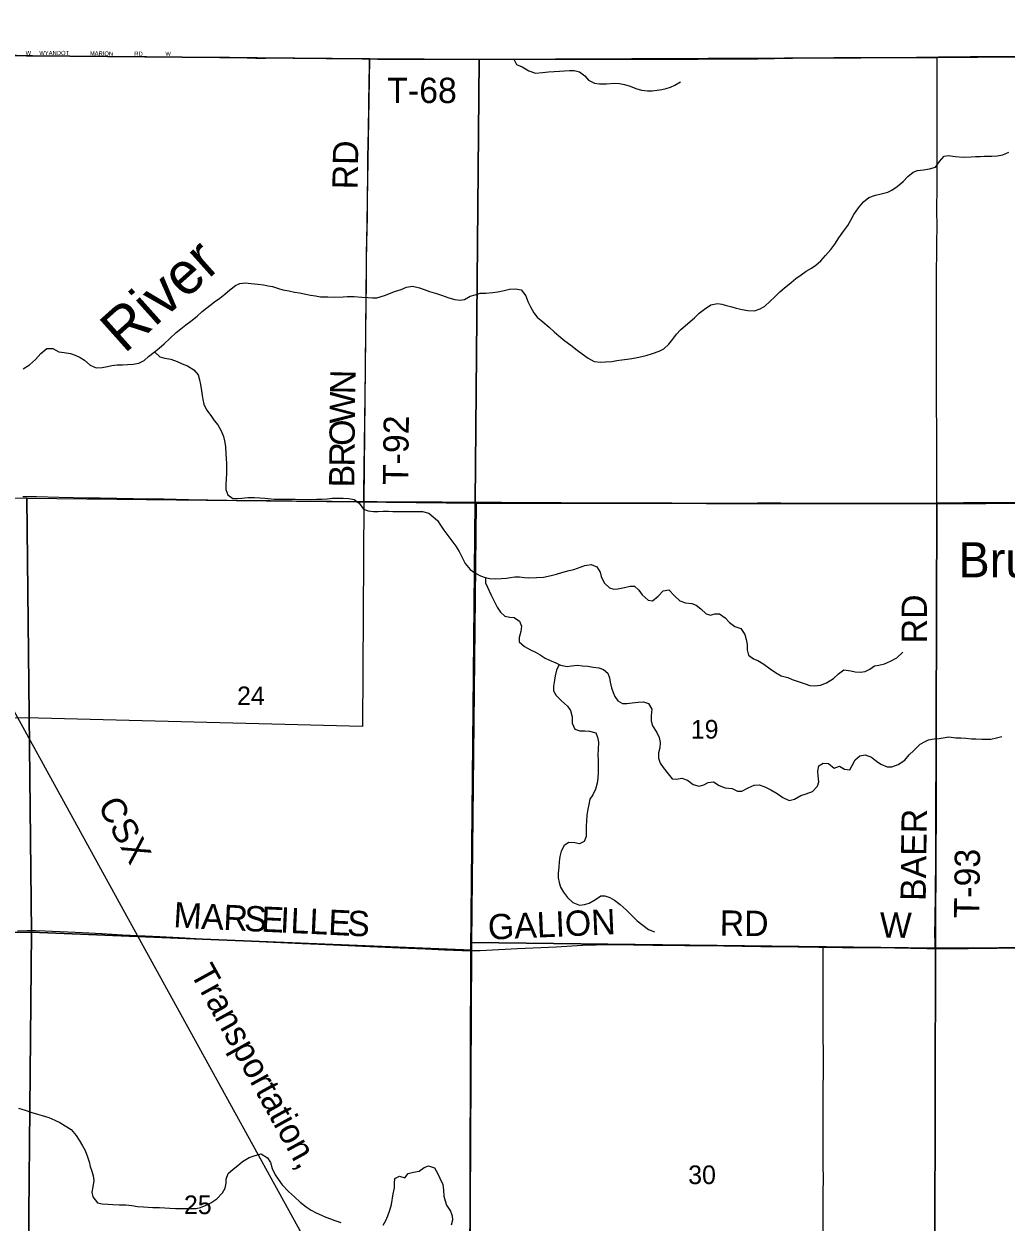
# Model space of a CAD drawing. Extents: x 1584893 to 1934202, y 663575 to 1091909.
# Drawn here: x 1772199 to 1783850, y 971203 to 985416 of the extents above; entities that cross this region are included whole.
import ezdxf

# ---------------------------------------------------------------- set-up
doc = ezdxf.new("R2010")
doc.units = 0
for name, color, linetype in [('GM_X_Adjacent_County', 7, 'Continuous'), ('GM_X_City_Street', 7, 'Continuous'), ('GM_X_City_Street_Text', 7, 'Continuous'), ('GM_X_Corporation', 7, 'Continuous'), ('GM_X_County', 7, 'Continuous'), ('GM_X_County_Road', 7, 'Continuous'), ('GM_X_County_Road_Text', 7, 'Continuous'), ('GM_X_Minor_River', 7, 'Continuous'), ('GM_X_Minor_River_Text', 7, 'Continuous'), ('GM_X_Rail_Line', 7, 'Continuous'), ('GM_X_Rail_Line_Text', 7, 'Continuous'), ('GM_X_Section', 7, 'Continuous'), ('GM_X_Section_Text', 7, 'Continuous'), ('GM_X_State_Route', 7, 'Continuous'), ('GM_X_Township', 7, 'Continuous'), ('GM_X_Township_Road', 7, 'Continuous'), ('GM_X_Township_Road_Text', 7, 'Continuous'), ('GM_X_Unincorporated_Text', 7, 'Continuous')]:
    doc.layers.add(name, color=color, linetype=linetype)

msp = doc.modelspace()

# ---------------------------------------------------------------- linework, layer by layer
at = {"layer": 'GM_X_Adjacent_County'}
msp.add_lwpolyline([(1798963, 1000818), (1798919, 995550), (1798958, 993982), (1798961, 990392), (1798944, 985119), (1793655, 985091), (1790446, 985072), (1788294, 985063), (1785879, 985049), (1785146, 985038), (1784945, 985035), (1783032, 985019), (1777600, 984996), (1776297, 985001), (1772302, 985037), (1771919, 985044), (1771012, 985062), (1767041, 985145), (1761103, 985171), (1756190, 985192)], dxfattribs=at)
at = {"layer": 'GM_X_City_Street'}
for points in [[(1771012, 985062), (1771168, 985059), (1771413, 985053), (1771919, 985044), (1772230, 985036), (1772273, 985036), (1772302, 985037)], [(1772302, 985037), (1772380, 985037), (1772948, 985033), (1773194, 985031), (1773651, 985029), (1773852, 985028), (1774030, 985027), (1774342, 985024), (1774473, 985023), (1774637, 985021), (1774949, 985012), (1775064, 985012), (1775277, 985014), (1775392, 985012), (1775556, 985009), (1775785, 985007), (1775900, 985006), (1776097, 985005), (1776212, 985002), (1776297, 985001)]]:
    msp.add_lwpolyline(points, dxfattribs=at)
at = {"layer": 'GM_X_Corporation'}
msp.add_lwpolyline([(1766961, 977231), (1766970, 979846), (1766980, 980279), (1766988, 980837), (1766989, 981036), (1767041, 985145), (1771012, 985062), (1771919, 985044), (1772302, 985037), (1776297, 985001), (1776257, 982591), (1776230, 979751), (1776216, 977083), (1772218, 977183), (1770900, 977182)], close=True, dxfattribs=at)
at = {"layer": 'GM_X_County'}
msp.add_lwpolyline([(1756190, 985192), (1761103, 985171), (1767041, 985145), (1771012, 985062), (1771919, 985044), (1772302, 985037), (1776297, 985001), (1777600, 984996), (1783032, 985019), (1784945, 985035), (1785146, 985038), (1785879, 985049), (1788294, 985063), (1790446, 985072), (1793655, 985091), (1798944, 985119), (1804246, 985060), (1804440, 985061), (1804717, 985058), (1805634, 985060), (1809554, 985051), (1810918, 985033)], dxfattribs=at)
at = {"layer": 'GM_X_County_Road'}
for points in [[(1772123, 974659), (1772237, 974662), (1772336, 974663), (1772451, 974658), (1772893, 974636), (1773123, 974624), (1773368, 974611), (1773549, 974602), (1773811, 974589), (1774040, 974577), (1774368, 974560), (1774908, 974533), (1775498, 974507), (1775695, 974498), (1775957, 974487), (1776301, 974471), (1776662, 974456), (1776957, 974444), (1777186, 974433), (1777399, 974424), (1777498, 974423), (1777508, 974423)], [(1777508, 974423), (1777612, 974426), (1778055, 974446), (1778513, 974469), (1778825, 974486), (1778989, 974493), (1779120, 974495), (1779432, 974492), (1779661, 974489), (1779858, 974487), (1780039, 974484), (1780285, 974482), (1780941, 974473), (1781384, 974468), (1781630, 974465), (1781679, 974464)], [(1781679, 974464), (1781909, 974461), (1782138, 974458), (1782532, 974454), (1782909, 974449), (1783007, 974449)], [(1781679, 971100), (1781679, 971255), (1781680, 971411), (1781682, 971534), (1781683, 971735), (1781682, 971856), (1781682, 971990), (1781680, 972188), (1781679, 972448), (1781680, 972559), (1781682, 972698), (1781682, 972829), (1781683, 972936), (1781683, 973084), (1781682, 973531), (1781682, 973707), (1781681, 973923), (1781681, 974183), (1781679, 974390), (1781679, 974445), (1781679, 974464)], [(1783007, 974449), (1783155, 974448), (1783401, 974449), (1783598, 974452), (1783746, 974453), (1783877, 974454), (1784123, 974456), (1784385, 974458), (1784763, 974460), (1785156, 974465), (1785632, 974469), (1786387, 974476), (1787043, 974483), (1787797, 974489), (1788240, 974493), (1788618, 974494), (1788733, 974494), (1788839, 974491)]]:
    msp.add_lwpolyline(points, dxfattribs=at)
at = {"layer": 'GM_X_Minor_River'}
for points in [[(1778009, 984997), (1778041, 984935), (1778111, 984908), (1778190, 984859), (1778268, 984832), (1778352, 984842), (1778422, 984849), (1778488, 984854), (1778552, 984856), (1778613, 984859), (1778669, 984862), (1778725, 984862), (1778789, 984849), (1778852, 984800), (1778896, 984750), (1778969, 984713), (1779025, 984704), (1779108, 984706), (1779200, 984713), (1779264, 984710), (1779322, 984699), (1779390, 984679), (1779459, 984650), (1779527, 984631), (1779595, 984622), (1779653, 984624), (1779711, 984629), (1779768, 984639), (1779818, 984650), (1779870, 984668), (1779920, 984689), (1779987, 984731)], [(1777010, 982243), (1777092, 982220), (1777153, 982198), (1777239, 982167), (1777311, 982146), (1777369, 982139), (1777425, 982147), (1777494, 982188), (1777550, 982204), (1777610, 982221), (1777680, 982224), (1777762, 982231), (1777819, 982239), (1777895, 982254), (1777961, 982269), (1778031, 982275), (1778099, 982260), (1778154, 982191), (1778178, 982123), (1778209, 982060), (1778248, 981990), (1778288, 981937), (1778353, 981881), (1778429, 981818), (1778488, 981765), (1778544, 981718), (1778617, 981657), (1778687, 981605), (1778760, 981548), (1778822, 981501), (1778892, 981450), (1778965, 981413), (1779037, 981405), (1779097, 981406), (1779174, 981413), (1779232, 981423), (1779292, 981432), (1779354, 981439), (1779412, 981449), (1779472, 981458), (1779529, 981470), (1779581, 981483), (1779657, 981506), (1779733, 981536), (1779790, 981563), (1779848, 981619), (1779897, 981678), (1779940, 981734), (1779988, 981786), (1780073, 981861), (1780154, 981930), (1780209, 981986), (1780273, 982033), (1780346, 982083), (1780426, 982100), (1780480, 982090), (1780532, 982077), (1780596, 982060), (1780648, 982046), (1780720, 982029), (1780788, 982018), (1780864, 982013), (1780934, 982035), (1780988, 982070), (1781047, 982124), (1781106, 982179), (1781166, 982237), (1781219, 982282), (1781302, 982348), (1781358, 982397), (1781419, 982439), (1781479, 982482), (1781542, 982518), (1781592, 982555), (1781651, 982605), (1781707, 982670), (1781770, 982742), (1781819, 982804), (1781868, 982879), (1781927, 982961), (1781973, 983027), (1782012, 983098), (1782043, 983156), (1782098, 983236), (1782160, 983307), (1782223, 983357), (1782301, 983384), (1782354, 983396), (1782446, 983419), (1782496, 983444), (1782557, 983488), (1782629, 983547), (1782684, 983607), (1782747, 983658), (1782801, 983676), (1782871, 983687), (1782941, 983696), (1783014, 983716), (1783062, 983783), (1783115, 983849), (1783167, 983856)], [(1783167, 983856), (1783245, 983842), (1783345, 983837), (1783437, 983840), (1783489, 983843), (1783542, 983845), (1783592, 983846), (1783680, 983849), (1783746, 983851), (1783810, 983864), (1783882, 983895)], [(1772191, 981326), (1772264, 981373), (1772334, 981435), (1772399, 981508), (1772470, 981564), (1772540, 981565), (1772614, 981528), (1772675, 981517), (1772751, 981507), (1772805, 981488), (1772865, 981459), (1772917, 981427), (1772984, 981368), (1773054, 981337), (1773126, 981340), (1773190, 981352), (1773241, 981363), (1773305, 981371), (1773369, 981374), (1773429, 981377), (1773495, 981381), (1773563, 981392), (1773626, 981424), (1773678, 981471), (1773743, 981523), (1773801, 981568), (1773862, 981620), (1773931, 981685), (1774005, 981754), (1774060, 981798), (1774118, 981846), (1774179, 981889), (1774252, 981948), (1774312, 982004), (1774458, 982119), (1774524, 982162), (1774581, 982212), (1774643, 982261), (1774710, 982315), (1774760, 982338), (1774822, 982346), (1774896, 982337), (1774972, 982328), (1775040, 982321), (1775096, 982309), (1775148, 982302), (1775218, 982277), (1775272, 982261), (1775342, 982250), (1775410, 982235), (1775466, 982225), (1775522, 982216), (1775598, 982197), (1775656, 982189), (1775718, 982180), (1775804, 982177), (1775884, 982174), (1775984, 982179), (1776034, 982183), (1776116, 982184), (1776206, 982175), (1776280, 982172), (1776332, 982168), (1776384, 982167), (1776477, 982196), (1776527, 982216), (1776595, 982241), (1776672, 982267), (1776738, 982294), (1776810, 982307), (1776890, 982286), (1776948, 982266), (1777010, 982243)], [(1773746, 981525), (1773810, 981468), (1773872, 981451), (1773942, 981438), (1774018, 981410), (1774074, 981385), (1774141, 981360), (1774215, 981313), (1774264, 981253), (1774280, 981194), (1774293, 981140), (1774307, 981064), (1774314, 981010), (1774322, 980959), (1774333, 980907), (1774364, 980837), (1774414, 980770), (1774457, 980713), (1774499, 980661), (1774540, 980590), (1774565, 980522), (1774579, 980470), (1774588, 980405), (1774593, 980313), (1774597, 980261), (1774600, 980197), (1774603, 980135), (1774603, 980076), (1774598, 980022), (1774595, 979948), (1774595, 979892), (1774616, 979828), (1774676, 979787), (1774732, 979788), (1774782, 979792), (1774856, 979799), (1774934, 979800), (1774996, 979796), (1775062, 979789), (1775166, 979780), (1775228, 979777), (1775290, 979779), (1775417, 979777), (1775599, 979776), (1775671, 979779), (1775733, 979780), (1775797, 979784), (1775857, 979789), (1775925, 979792), (1775987, 979790), (1776053, 979785), (1776117, 979776), (1776177, 979730), (1776228, 979661), (1776284, 979640), (1776346, 979634), (1776402, 979631), (1776460, 979635), (1776524, 979636), (1776574, 979633), (1776792, 979631), (1776857, 979633), (1776925, 979632), (1777001, 979613), (1777052, 979570), (1777106, 979526), (1777141, 979469), (1777179, 979411), (1777226, 979346), (1777275, 979285), (1777321, 979221), (1777360, 979156), (1777396, 979086), (1777433, 979017), (1777494, 978944), (1777546, 978906), (1777614, 978869), (1777669, 978850), (1777725, 978838), (1777795, 978835), (1777861, 978836), (1777922, 978842), (1777972, 978851), (1778022, 978857), (1778076, 978856), (1778136, 978850), (1778188, 978845), (1778280, 978848), (1778364, 978855), (1778452, 978871), (1778515, 978888), (1778581, 978907), (1778667, 978931), (1778723, 978944), (1778854, 978993), (1778926, 979002), (1778996, 978975), (1779033, 978911), (1779045, 978861), (1779082, 978786), (1779144, 978727)], [(1777673, 978850), (1777673, 978784), (1777743, 978639), (1777773, 978577), (1777812, 978498), (1777851, 978438), (1777905, 978389), (1777963, 978380), (1778015, 978376), (1778078, 978333), (1778102, 978271), (1778095, 978207), (1778072, 978137), (1778074, 978087), (1778139, 978032), (1778207, 977993), (1778267, 977962), (1778323, 977932), (1778382, 977893), (1778434, 977868), (1778508, 977836), (1778566, 977809), (1778643, 977794), (1778696, 977802), (1778764, 977809), (1778824, 977802), (1778888, 977798), (1778950, 977787), (1779020, 977778), (1779074, 977758), (1779127, 977713), (1779147, 977657), (1779154, 977606), (1779169, 977540), (1779189, 977486), (1779210, 977436), (1779244, 977385), (1779298, 977356), (1779352, 977354), (1779416, 977363), (1779486, 977371), (1779548, 977376), (1779610, 977353), (1779647, 977287), (1779638, 977207), (1779638, 977149), (1779655, 977088), (1779707, 977010), (1779736, 976953), (1779745, 976891), (1779741, 976829), (1779728, 976771), (1779725, 976705), (1779745, 976646), (1779784, 976596), (1779842, 976519), (1779887, 976462), (1779941, 976456), (1780003, 976467), (1780069, 976443), (1780137, 976392), (1780210, 976373), (1780265, 976388), (1780315, 976418), (1780379, 976425), (1780447, 976383), (1780519, 976352), (1780601, 976345), (1780664, 976316), (1780716, 976314), (1780791, 976355), (1780861, 976386), (1780921, 976388), (1780989, 976365), (1781061, 976332), (1781133, 976285), (1781200, 976239), (1781276, 976204), (1781342, 976219), (1781415, 976262), (1781479, 976284), (1781553, 976311), (1781612, 976375), (1781629, 976427), (1781621, 976497), (1781616, 976553), (1781628, 976613), (1781679, 976647), (1781745, 976642), (1781812, 976589), (1781873, 976609), (1781932, 976576), (1781996, 976567), (1782025, 976619), (1782058, 976685), (1782116, 976734), (1782178, 976746), (1782252, 976719), (1782314, 976670), (1782365, 976634), (1782441, 976605)], [(1779144, 978727), (1779196, 978711), (1779246, 978714), (1779324, 978729), (1779392, 978747), (1779442, 978748), (1779494, 978700), (1779533, 978643), (1779603, 978582), (1779655, 978572), (1779721, 978629), (1779784, 978691), (1779848, 978704), (1779918, 978631), (1779981, 978574), (1780049, 978550), (1780121, 978541), (1780173, 978520), (1780228, 978478), (1780292, 978419), (1780344, 978404), (1780394, 978418), (1780450, 978417), (1780517, 978372), (1780571, 978314), (1780633, 978267), (1780702, 978244), (1780752, 978174), (1780767, 978113), (1780778, 978053), (1780780, 977993), (1780793, 977927), (1780855, 977884), (1780907, 977865), (1780976, 977823), (1781050, 977766), (1781115, 977723), (1781183, 977684), (1781261, 977663), (1781313, 977641), (1781383, 977616), (1781468, 977587), (1781524, 977568), (1781578, 977564), (1781648, 977573), (1781721, 977598), (1781801, 977652), (1781864, 977707), (1781927, 977753), (1782007, 977740), (1782061, 977731), (1782123, 977725), (1782179, 977734), (1782233, 977760), (1782289, 977801), (1782340, 977811), (1782406, 977826), (1782478, 977855), (1782553, 977897), (1782624, 977964)], [(1778547, 977818), (1778517, 977751), (1778502, 977683), (1778492, 977631), (1778483, 977559), (1778482, 977503), (1778514, 977451), (1778575, 977388), (1778647, 977323), (1778682, 977271), (1778701, 977198), (1778703, 977122), (1778734, 977051), (1778794, 977031), (1778854, 977030), (1778908, 977026), (1778982, 977007), (1779005, 976954), (1779015, 976894), (1779012, 976808), (1779009, 976746), (1779012, 976680), (1779011, 976535), (1779008, 976469), (1779000, 976411), (1778981, 976339), (1778946, 976272), (1778911, 976220), (1778901, 976158), (1778888, 976102), (1778875, 976030), (1778871, 975960), (1778868, 975905), (1778867, 975775), (1778846, 975717), (1778790, 975688), (1778736, 975700), (1778662, 975705), (1778609, 975670), (1778571, 975604), (1778558, 975538), (1778549, 975478), (1778543, 975414), (1778538, 975342), (1778537, 975287), (1778547, 975229), (1778564, 975177), (1778598, 975118), (1778649, 975052), (1778709, 974993), (1778788, 974962), (1778848, 974970), (1778903, 974985), (1778979, 975030), (1779042, 975074), (1779092, 975071), (1779150, 975053), (1779203, 975022), (1779271, 974969), (1779342, 974908), (1779412, 974840), (1779473, 974775), (1779539, 974724), (1779608, 974675), (1779678, 974644)], [(1782441, 976605), (1782493, 976602), (1782572, 976632), (1782648, 976683), (1782701, 976744), (1782756, 976796), (1782830, 976871), (1782881, 976901), (1782931, 976923), (1782997, 976936), (1783055, 976939), (1783105, 976947), (1783170, 976958), (1783254, 976949), (1783314, 976947), (1783372, 976942), (1783440, 976937), (1783490, 976935), (1783562, 976930), (1783618, 976930), (1783668, 976933), (1783738, 976948), (1783800, 976964)], [(1772136, 972552), (1772212, 972529), (1772292, 972502), (1772358, 972484), (1772416, 972465), (1772492, 972442), (1772565, 972413), (1772623, 972383), (1772689, 972346), (1772760, 972299), (1772818, 972230), (1772853, 972176), (1772894, 972105), (1772926, 972051), (1772951, 971978), (1772971, 971916), (1772986, 971862), (1773003, 971806), (1773019, 971749), (1773026, 971697), (1773016, 971621), (1773005, 971557), (1773016, 971501), (1773072, 971432), (1773128, 971417), (1773194, 971415), (1773254, 971410), (1773334, 971405), (1773408, 971407), (1773480, 971398)], [(1773480, 971398), (1773546, 971387), (1773618, 971382), (1773672, 971380), (1773728, 971377), (1773808, 971376), (1773872, 971372), (1773930, 971369), (1773998, 971364), (1774070, 971364), (1774130, 971365), (1774240, 971364), (1774294, 971376), (1774361, 971403), (1774415, 971430), (1774488, 971478), (1774556, 971549), (1774585, 971605), (1774598, 971663), (1774598, 971713), (1774621, 971779), (1774681, 971829), (1774738, 971874), (1774793, 971920), (1774871, 971969), (1774941, 971992), (1775012, 972010), (1775087, 971965), (1775123, 971910), (1775142, 971836), (1775181, 971761), (1775213, 971711), (1775264, 971644), (1775339, 971565), (1775409, 971500), (1775476, 971438), (1775546, 971383), (1775605, 971344), (1775665, 971313), (1775727, 971285), (1775781, 971260), (1775837, 971240), (1775888, 971223), (1775960, 971196)], [(1776462, 971167), (1776491, 971223), (1776516, 971275), (1776540, 971343), (1776559, 971409), (1776580, 971539), (1776595, 971609), (1776596, 971659), (1776598, 971721), (1776653, 971746), (1776719, 971728), (1776757, 971779), (1776819, 971795), (1776886, 971806), (1776948, 971848), (1777000, 971869), (1777070, 971846), (1777109, 971776), (1777131, 971722), (1777168, 971649), (1777178, 971581), (1777181, 971511), (1777194, 971456), (1777212, 971402), (1777259, 971333), (1777278, 971275), (1777284, 971225), (1777267, 971165)]]:
    msp.add_lwpolyline(points, dxfattribs=at)
at = {"layer": 'GM_X_Rail_Line'}
msp.add_lwpolyline([(1783640, 956258), (1783519, 956485), (1783352, 956796), (1782890, 957631), (1782729, 957923), (1782630, 958110), (1782495, 958363), (1782431, 958480), (1782385, 958557), (1780582, 961821), (1780198, 962518), (1779487, 963811), (1778628, 965371), (1777525, 967376), (1776542, 969162), (1773550, 974593), (1770672, 979824), (1769928, 981176), (1769339, 982253), (1768902, 983060), (1768396, 983986), (1767773, 985118)], dxfattribs=at)
at = {"layer": 'GM_X_Section'}
for points in [[(1772232, 979790), (1772288, 974643), (1766937, 974569), (1766983, 979866)], [(1777563, 979732), (1777507, 974521), (1777507, 974427), (1772288, 974643), (1772232, 979790)], [(1783030, 979724), (1783012, 974453), (1777507, 974521), (1777563, 979732)], [(1788265, 979759), (1788243, 974478), (1783012, 974453), (1783030, 979724)], [(1766937, 974569), (1772288, 974643), (1772236, 969202), (1766881, 969263)], [(1772288, 974643), (1777507, 974427), (1777480, 969162), (1772236, 969202)], [(1777507, 974521), (1783012, 974453), (1783001, 969162), (1777480, 969162), (1777507, 974427)], [(1783012, 974453), (1788243, 974478), (1788271, 969190), (1783001, 969162)]]:
    msp.add_lwpolyline(points, close=True, dxfattribs=at)
at = {"layer": 'GM_X_State_Route'}
for points in [[(1772185, 979811), (1772349, 979809), (1772611, 979804), (1772955, 979796), (1773103, 979794), (1773300, 979791), (1773496, 979788), (1773857, 979782), (1774152, 979776), (1774611, 979768), (1775119, 979761), (1775643, 979755), (1775856, 979753), (1776053, 979752), (1776184, 979751), (1776230, 979751)], [(1776230, 979751), (1776391, 979749), (1776850, 979748), (1777161, 979745), (1777440, 979743), (1777570, 979744), (1777653, 979744), (1777866, 979743), (1778276, 979740), (1778572, 979739), (1778883, 979736), (1779260, 979736), (1779884, 979735), (1780408, 979733), (1780900, 979734), (1781179, 979735), (1781474, 979732), (1781851, 979731), (1782393, 979731), (1782704, 979733), (1783030, 979736), (1783032, 979736), (1783344, 979737), (1783721, 979738), (1783992, 979740)]]:
    msp.add_lwpolyline(points, dxfattribs=at)
at = {"layer": 'GM_X_Township'}
for points in [[(1756190, 985192), (1761103, 985171), (1767041, 985145), (1771012, 985062), (1771919, 985044), (1772302, 985037), (1776297, 985001), (1777600, 984996), (1777553, 979747), (1777500, 974427), (1777484, 969144), (1777421, 963835), (1774761, 963889), (1772077, 963906), (1768920, 963948), (1764172, 963989), (1755145, 964022)], [(1789219, 963906), (1781614, 963853), (1780304, 963849), (1779496, 963806), (1777421, 963835), (1777484, 969144), (1777500, 974427), (1777553, 979747), (1777600, 984996), (1783032, 985019), (1784945, 985035)]]:
    msp.add_lwpolyline(points, dxfattribs=at)
at = {"layer": 'GM_X_Township_Road'}
for points in [[(1776230, 979751), (1776230, 979802), (1776231, 979873), (1776235, 980152), (1776239, 980431), (1776244, 980710), (1776247, 981022), (1776251, 981268), (1776252, 981449), (1776253, 981580), (1776255, 981761), (1776258, 982057), (1776261, 982369), (1776262, 982500), (1776263, 982631), (1776264, 982713), (1776270, 982960), (1776273, 983140), (1776274, 983337), (1776277, 983649), (1776280, 983830), (1776286, 984158), (1776291, 984454), (1776295, 984750), (1776297, 984897), (1776297, 985001)], [(1776297, 985001), (1776392, 985000), (1776507, 984999), (1776769, 984999), (1776933, 984999), (1777081, 984999), (1777360, 984998), (1777623, 984998), (1777627, 984998)], [(1777627, 984998), (1778029, 984998), (1778328, 984998), (1778487, 984998), (1778739, 984999), (1778985, 984999), (1779165, 984999), (1779282, 985000), (1779494, 985000), (1779937, 984999), (1780199, 985000), (1780413, 985001), (1780905, 985003), (1781102, 985006), (1781315, 985012), (1781552, 985016), (1781808, 985019), (1781988, 985020), (1782198, 985019), (1782546, 985020), (1782789, 985021), (1782973, 985022), (1783004, 985022), (1783019, 985023), (1783034, 985024)], [(1783030, 979736), (1783029, 979884), (1783027, 980162), (1783028, 980359), (1783027, 980507), (1783025, 980983), (1783026, 981179), (1783026, 981343), (1783025, 981475), (1783024, 981606), (1783023, 981737), (1783024, 981999), (1783025, 982180), (1783026, 982311), (1783026, 982491), (1783027, 982688), (1783028, 982836), (1783031, 983000), (1783030, 983213), (1783032, 983475), (1783032, 983646), (1783033, 983756), (1783033, 983853), (1783033, 983967), (1783033, 984082), (1783033, 984197), (1783032, 984443), (1783033, 984640), (1783033, 984837), (1783034, 985024)], [(1783034, 985024), (1783049, 985025), (1783066, 985026), (1783181, 985026), (1783427, 985029), (1783723, 985030), (1783904, 985031), (1784129, 985036), (1784289, 985039), (1784393, 985039), (1784571, 985041), (1784766, 985044), (1784848, 985041), (1784866, 985042), (1784882, 985044), (1784892, 985046), (1784899, 985049), (1784914, 985057), (1784930, 985067)], [(1783007, 974449), (1783008, 974472), (1783008, 974539), (1783007, 974604), (1783010, 974817), (1783011, 974932), (1783012, 974949), (1783013, 975080), (1783014, 975178), (1783014, 975227), (1783017, 975407), (1783019, 975587), (1783021, 975718), (1783021, 975767), (1783023, 975832), (1783024, 975914), (1783024, 976061), (1783023, 976422), (1783025, 976832), (1783025, 977046), (1783026, 977374), (1783025, 977538), (1783024, 977751), (1783024, 977997), (1783026, 978571), (1783028, 978932), (1783029, 979277), (1783029, 979424), (1783030, 979572), (1783030, 979736)]]:
    msp.add_lwpolyline(points, dxfattribs=at)

# ---------------------------------------------------------------- texts
at = {"layer": 'GM_X_City_Street_Text'}
for s, rotation, p in [('W', 0, (1772219, 985047)), ('WYANDOT', 0, (1772381, 985047)), ('MARION', 358.9717, (1772980, 985043)), ('RD', 0, (1773508, 985038)), ('W', 0, (1773877, 985038))]:
    msp.add_text(s, height=50, rotation=rotation, dxfattribs=at).set_placement(p)
at = {"layer": 'GM_X_County_Road_Text'}
for s, rotation, p in [('M', 356.5659, (1773967, 974701)), ('A', 357.3504, (1774297, 974681)), ('R', 357.3523, (1774560, 974669)), ('S', 357.3526, (1774806, 974657)), ('E', 357.3505, (1775009, 974648)), ('I', 357.345, (1775233, 974638)), ('L', 357.3538, (1775356, 974632)), ('L', 357.3505, (1775580, 974622)), ('E', 357.3505, (1775804, 974611)), ('S', 357.3489, (1776028, 974601)), ('GALION', 2.5127, (1777709, 974552)), ('RD', 359.5064, (1780452, 974600)), ('W', 359.2708, (1782351, 974578))]:
    msp.add_text(s, height=300, rotation=rotation, dxfattribs=at).set_placement(p)
at = {"layer": 'GM_X_Minor_River_Text'}
msp.add_text('River', height=500.1, rotation=41.7941, dxfattribs=at).set_placement((1773391, 981497))
at = {"layer": 'GM_X_Rail_Line_Text'}
for s, rotation, p in [('CSX', 298.6946, (1773068, 976146)), ('Transportation,', 298.8586, (1774165, 974159))]:
    msp.add_text(s, height=299, rotation=rotation, dxfattribs=at).set_placement(p)
at = {"layer": 'GM_X_Section_Text'}
for s, p in [('24', (1774727, 977335)), ('19', (1780110, 976938)), ('30', (1780079, 971653)), ('25', (1774097, 971297))]:
    msp.add_text(s, height=221, rotation=0, dxfattribs=at).set_placement(p)
at = {"layer": 'GM_X_Township_Road_Text'}
for s, rotation, p in [('T-68', 0, (1776509, 984478)), ('RD', 89.014, (1776157, 983452)), ('N', 88.816, (1776128, 981021)), ('W', 89.4383, (1776125, 980674)), ('T-92', 89.2931, (1776756, 979945)), ('O', 89.439, (1776122, 980410)), ('R', 89.4412, (1776120, 980164)), ('B', 89.4379, (1776118, 979917)), ('RD', 90, (1782911, 978068)), ('BAER', 89.2357, (1782897, 975011)), ('T-93', 89.3111, (1783532, 974804))]:
    msp.add_text(s, height=300, rotation=rotation, dxfattribs=at).set_placement(p)
at = {"layer": 'GM_X_Unincorporated_Text'}
msp.add_text('Brush Ridge', height=417, rotation=0, dxfattribs=at).set_placement((1783284, 978851))

doc.saveas('drawing.dxf')
